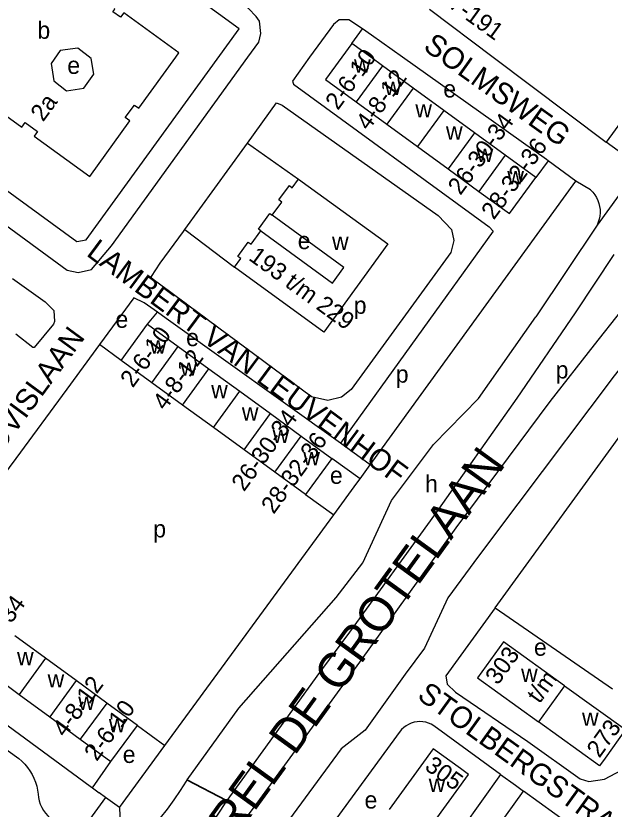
# Model space of a CAD drawing. Extents: x 159700 to 161346, y 381730 to 382922.
# Drawn here: x 160111.3 to 160249.2, y 382258.8 to 382442.9 of the extents above; entities that cross this region are included whole.
import ezdxf

# ---------------------------------------------------------------- set-up
doc = ezdxf.new("R2010")
doc.units = 0
for name, color, linetype in [('BLT_Basislijn', 7, 'Continuous'), ('BLT_Bebouwing', 7, 'Continuous'), ('BLT_Centroide', 7, 'Continuous'), ('BLT_Huisnummer', 7, 'Continuous'), ('BLT_Huisnummer_reeks', 7, 'Continuous'), ('BLT_Onderverdeling_panden', 7, 'Continuous'), ('BLT_Straatnaam', 7, 'Continuous'), ('BLT_Straatnaam_hoofdweg', 7, 'Continuous'), ('BLT_Vlakafsluiter', 7, 'Continuous')]:
    doc.layers.add(name, color=color, linetype=linetype)

msp = doc.modelspace()

# ---------------------------------------------------------------- linework, layer by layer
at = {"layer": 'BLT_Basislijn'}
for p, q in [((160189.26, 382436.52), (160191.7, 382439.88)), ((160165.04, 382413.38), (160176.87, 382405.03)), ((160252.43, 382410.59), (160248.24, 382413.61)), ((160234.75, 382409.29), (160231.92, 382405.42)), ((160241.19, 382404.58), (160234.75, 382409.29)), ((160193.53, 382338.74), (160241.19, 382404.58)), ((160244.62, 382402.5), (160241.19, 382404.58)), ((160150.52, 382393.35), (160162.02, 382384.61)), ((160246.12, 382394.33), (160231.92, 382373.05)), ((160250.04, 382387.54), (160241.05, 382374.01)), ((160141.86, 382371.33), (160144.19, 382374.14)), ((160241.05, 382374.01), (160227.5, 382354.17)), ((160130.73, 382366.61), (160123.15, 382356.29)), ((160135.76, 382362.95), (160130.73, 382366.61)), ((160222.52, 382305.55), (160263.56, 382362.17)), ((160123.15, 382356.29), (160111.33, 382340.21)), ((160227.5, 382354.17), (160208.45, 382327.12)), ((160235.17, 382353.39), (160213.4, 382324.1)), ((160193.53, 382338.74), (160186.59, 382343.72)), ((160111.33, 382340.21), (160108.18, 382335.98)), ((160191.15, 382335.45), (160184.59, 382340.23)), ((160191.15, 382335.45), (160193.53, 382338.74)), ((160178.49, 382331.85), (160185.05, 382327.12)), ((160145.86, 382273.59), (160185.05, 382327.12)), ((160213.4, 382324.1), (160191.02, 382292.94)), ((160222.52, 382305.55), (160249.67, 382286.74)), ((160191.02, 382292.94), (160167.79, 382261.09)), ((160089.95, 382286.38), (160111.96, 382270.56)), ((160139.51, 382278.26), (160145.86, 382273.59)), ((160223.73, 382266.87), (160208.27, 382278.18)), ((160200.46, 382276.89), (160179.29, 382248.03)), ((160135.33, 382259.22), (160145.86, 382273.59)), ((160129.06, 382263.8), (160133.36, 382269.85)), ((160223.73, 382266.87), (160191.03, 382221.18)), ((160129.06, 382263.8), (160130.61, 382262.6)), ((160132.12, 382261.51), (160130.61, 382262.6)), ((160221.28, 382252.22), (160229.09, 382263)), ((160135.33, 382259.22), (160132.12, 382261.51)), ((160167.79, 382261.09), (160160.39, 382250.98))]:
    msp.add_line(p, q, dxfattribs=at)
for points in [[(160055.58, 382436.89), (160053.86, 382434.1), (160054.93, 382433.33), (160088.85, 382409.04), (160123.19, 382383.92), (160125.73, 382383.39), (160128.86, 382384.06), (160133.46, 382389.51), (160165.14, 382433.33), (160167.65, 382436.8), (160168.16, 382438.78), (160167.81, 382441.67), (160167.07, 382442.79), (160165.27, 382444.61), (160155.77, 382451.87), (160099.41, 382492.45), (160096.79, 382493.83), (160095.82, 382492.52)], [(160059.6, 382438.55), (160125.46, 382390.57), (160127.6, 382390.97), (160163.12, 382439.91), (160095.62, 382488.95)], [(160293.83, 382476.2), (160293.16, 382475.27), (160262.61, 382433.33), (160248.24, 382413.61)], [(160207.26, 382444.45), (160222.03, 382433.33), (160248.24, 382413.61)], [(160191.7, 382439.88), (160188.55, 382441.99), (160186.32, 382442.02), (160184.96, 382440.88), (160179.42, 382433.33), (160175.49, 382427.79), (160175.68, 382427.09), (160221.08, 382393.97), (160222.03, 382392.92), (160186.59, 382343.72)], [(160234.75, 382409.29), (160234.37, 382409.56), (160201.02, 382433.33), (160193.84, 382438.46), (160191.7, 382439.88)], [(160165.04, 382413.38), (160171.79, 382422.72), (160173.06, 382422.18), (160209.25, 382396.61), (160212.35, 382393.33), (160212.92, 382390.79), (160212.18, 382387.99), (160189.12, 382356.18), (160186.83, 382354.42), (160183.65, 382353.66), (160179.9, 382354.53), (160142.84, 382381.98), (160142.79, 382382.45), (160144.82, 382385.53), (160150.16, 382392.86), (160150.52, 382393.35)], [(160150.52, 382393.35), (160164.45, 382412.55), (160165.04, 382413.38)], [(160244.62, 382402.5), (160245.13, 382401.97), (160245.59, 382401.39), (160245.98, 382400.76), (160246.3, 382400.09), (160246.55, 382399.39), (160246.72, 382398.67), (160246.81, 382397.94), (160246.82, 382397.2), (160246.75, 382396.46), (160246.61, 382395.74), (160246.38, 382395.03), (160246.12, 382394.33)], [(160168.14, 382393.01), (160167.62, 382393.43), (160170.23, 382397.02), (160170.77, 382396.63)], [(160110.52, 382381.97), (160118.13, 382376.57), (160120.11, 382374.57), (160120.26, 382372.01), (160120.01, 382371.39), (160115.53, 382365.97), (160115.28, 382365.97), (160111.29, 382369.02)], [(160268.06, 382382.16), (160250.09, 382359.39), (160227.78, 382329.64), (160218.64, 382317.56)], [(160257.68, 382382.01), (160245.47, 382366.57), (160235.17, 382353.39)], [(160144.19, 382374.14), (160141.08, 382376.34), (160138.71, 382377.48), (160130.73, 382366.61)], [(160186.59, 382343.72), (160146.21, 382372.71), (160144.19, 382374.14)], [(160198.47, 382330.41), (160208.22, 382343.46), (160218.6, 382354.15), (160231.92, 382373.05)], [(160185.05, 382327.12), (160190.44, 382334.48), (160191.15, 382335.45)], [(160151.03, 382265.6), (160163, 382282.24), (160185.61, 382307.95), (160191.81, 382316), (160198.47, 382330.41)], [(160208.45, 382327.12), (160188.7, 382299.92), (160181.73, 382290.54)], [(160218.64, 382317.56), (160211.51, 382307.82), (160206.09, 382296.19), (160201.61, 382290.12)], [(160222.52, 382305.55), (160211.06, 382289.75), (160211.38, 382287.84), (160213.29, 382285.99), (160230.06, 382274.53), (160242.18, 382265.83), (160244.2, 382265.24), (160247.86, 382265.74), (160264.1, 382274.33), (160265.12, 382275.17), (160265.4, 382275.55)], [(160087.42, 382292.85), (160091.58, 382291.34), (160128.55, 382264.19), (160129.06, 382263.8)], [(160181.73, 382290.54), (160165.93, 382268.68), (160160.23, 382260.82)], [(160201.61, 382290.12), (160192.3, 382277.12), (160186.73, 382272.79), (160170.03, 382250.04)], [(160208.27, 382278.18), (160207.67, 382278.53), (160207.05, 382278.79), (160206.39, 382278.99), (160205.72, 382279.11), (160205.04, 382279.14), (160204.36, 382279.1), (160203.68, 382278.98), (160203.03, 382278.78), (160202.41, 382278.5), (160201.82, 382278.16), (160201.27, 382277.74), (160200.78, 382277.27), (160200.46, 382276.89)], [(160111.96, 382270.56), (160112.7, 382269.93), (160113.39, 382269.24), (160114.02, 382268.5), (160114.58, 382267.71), (160115.08, 382266.87), (160115.51, 382266), (160115.87, 382265.09), (160116.15, 382264.16), (160116.35, 382263.2), (160116.47, 382262.31)], [(160223.73, 382266.87), (160227.21, 382264.37), (160229.09, 382263)], [(160114.46, 382232.74), (160116.8, 382233.88), (160119.11, 382235.1), (160121.38, 382236.38), (160123.61, 382237.74), (160125.79, 382239.16), (160127.93, 382240.65), (160130.03, 382242.2), (160132.07, 382243.82), (160134.07, 382245.5), (160136.01, 382247.24), (160137.9, 382249.04), (160139.73, 382250.9), (160141.51, 382252.81), (160143.23, 382254.77), (160144.88, 382256.79), (160146.47, 382258.85), (160148, 382260.97), (160149.46, 382263.13), (160150.86, 382265.33), (160151, 382265.56)], [(160151, 382265.56), (160151.03, 382265.6)], [(160116.47, 382262.31), (160116.56, 382261.52), (160116.74, 382260.73), (160116.98, 382259.97), (160117.31, 382259.24), (160117.7, 382258.54), (160118.16, 382257.89), (160118.69, 382257.29), (160119.27, 382256.74), (160119.88, 382256.27)], [(160267.47, 382258.69), (160243.6, 382252.44), (160229.09, 382263)], [(160132.12, 382261.51), (160125.53, 382252.48), (160119.88, 382256.27)], [(160160.2, 382260.78), (160158.66, 382258.38), (160157.05, 382256.02), (160155.37, 382253.71), (160153.64, 382251.44), (160151.83, 382249.23), (160149.97, 382247.07), (160148.05, 382244.96), (160146.07, 382242.9), (160144.03, 382240.9), (160141.94, 382238.96), (160139.79, 382237.08), (160137.59, 382235.26), (160135.35, 382233.5), (160133.05, 382231.81), (160130.71, 382230.18), (160129.76, 382229.55)], [(160160.23, 382260.82), (160160.2, 382260.78)], [(160135.33, 382259.22), (160135.59, 382253.44), (160131.88, 382249.87)]]:
    msp.add_lwpolyline(points, dxfattribs=at)
at = {"layer": 'BLT_Bebouwing'}
for p, q in [((160203.48, 382426.15), (160196.37, 382431.33)), ((160210.59, 382420.97), (160203.48, 382426.15)), ((160190.24, 382422.93), (160197.35, 382417.74)), ((160217.7, 382415.78), (160210.59, 382420.97)), ((160197.35, 382417.74), (160204.46, 382412.56)), ((160224.81, 382410.6), (160217.7, 382415.78)), ((160204.46, 382412.56), (160211.57, 382407.38)), ((160231.92, 382405.42), (160224.81, 382410.6)), ((160211.57, 382407.38), (160218.68, 382402.19)), ((160135.76, 382362.95), (160141.86, 382371.33)), ((160141.86, 382371.33), (160148.98, 382366.15)), ((160148.98, 382366.15), (160156.1, 382360.97)), ((160142.88, 382357.77), (160135.76, 382362.95)), ((160156.1, 382360.97), (160163.23, 382355.78)), ((160150, 382352.58), (160142.88, 382357.77)), ((160163.23, 382355.78), (160170.35, 382350.6)), ((160157.12, 382347.4), (160150, 382352.58)), ((160170.35, 382350.6), (160177.47, 382345.41)), ((160164.25, 382342.21), (160157.12, 382347.4)), ((160177.47, 382345.41), (160184.59, 382340.23)), ((160171.37, 382337.03), (160164.25, 382342.21)), ((160184.59, 382340.23), (160178.49, 382331.85)), ((160178.49, 382331.85), (160171.37, 382337.03)), ((160118.2, 382293.84), (160111.1, 382299.03)), ((160125.3, 382288.65), (160118.2, 382293.84)), ((160104.95, 382290.62), (160112.05, 382285.43)), ((160132.41, 382283.45), (160125.3, 382288.65)), ((160112.05, 382285.43), (160119.15, 382280.23)), ((160139.51, 382278.26), (160132.41, 382283.45)), ((160119.15, 382280.23), (160126.26, 382275.04)), ((160133.36, 382269.85), (160139.51, 382278.26)), ((160126.26, 382275.04), (160133.36, 382269.85))]:
    msp.add_line(p, q, dxfattribs=at)
for points in [[(160099.75, 382426.44), (160112.67, 382417.06), (160113.45, 382418.13), (160116.31, 382416.06), (160115.54, 382415), (160128.43, 382405.64), (160137.78, 382418.52), (160136.7, 382419.3), (160138.81, 382422.22), (160139.83, 382421.48), (160148.43, 382433.33), (160149.15, 382434.32), (160136.32, 382443.63), (160135.58, 382442.61), (160133.84, 382443.87), (160134.28, 382444.49), (160134.12, 382444.61)], [(160189.26, 382436.52), (160186.93, 382433.33), (160183.13, 382428.11), (160190.24, 382422.93)], [(160196.37, 382431.33), (160193.62, 382433.33), (160189.26, 382436.52)], [(160176.87, 382405.03), (160197.61, 382389.99), (160182.78, 382369.54), (160162.02, 382384.61)], [(160170.77, 382396.63), (160173.01, 382399.71), (160172.34, 382400.19), (160174.76, 382403.53), (160175.43, 382403.04), (160176.87, 382405.03)], [(160218.68, 382402.19), (160225.8, 382397.01), (160231.92, 382405.42)], [(160168.14, 382393.01), (160184.78, 382380.91), (160187.42, 382384.53), (160170.77, 382396.63)], [(160162.02, 382384.61), (160163.47, 382386.6), (160162.8, 382387.08), (160165.23, 382390.42), (160165.9, 382389.93), (160168.14, 382393.01)], [(160238.59, 382287.46), (160224.46, 382297.64), (160219.42, 382290.68), (160218.4, 382289.26), (160232.54, 382279.07)], [(160238.59, 382287.46), (160252.72, 382277.28), (160247.97, 382270.68), (160246.68, 382268.88), (160232.54, 382279.07)], [(160206.07, 382252.8), (160216.28, 382266.89), (160214.44, 382268.23), (160208.07, 382272.81), (160197.87, 382258.75)]]:
    msp.add_lwpolyline(points, dxfattribs=at)
msp.add_lwpolyline([(160125.65, 382435.43), (160121.62, 382434.84), (160119.49, 382431.82), (160120.15, 382427.8), (160123.09, 382425.53), (160127.09, 382426.11), (160129.39, 382429.4), (160128.79, 382433.01)], close=True, dxfattribs=at)
at = {"layer": 'BLT_Onderverdeling_panden'}
for p, q in [((160196.37, 382431.33), (160190.24, 382422.93)), ((160203.48, 382426.15), (160197.35, 382417.74)), ((160210.59, 382420.97), (160204.46, 382412.56)), ((160217.7, 382415.78), (160211.57, 382407.38)), ((160224.81, 382410.6), (160218.68, 382402.19)), ((160142.88, 382357.77), (160148.98, 382366.15)), ((160150, 382352.58), (160156.1, 382360.97)), ((160157.12, 382347.4), (160163.23, 382355.78)), ((160164.25, 382342.21), (160170.35, 382350.6)), ((160171.37, 382337.03), (160177.47, 382345.41)), ((160118.2, 382293.84), (160112.05, 382285.43)), ((160125.3, 382288.65), (160119.15, 382280.23)), ((160238.59, 382287.46), (160232.54, 382279.07)), ((160132.41, 382283.45), (160126.26, 382275.04))]:
    msp.add_line(p, q, dxfattribs=at)
at = {"layer": 'BLT_Vlakafsluiter'}
for p, q in [((160258.48, 382411.43), (160246.12, 382394.33)), ((160160.2, 382260.78), (160151, 382265.56)), ((160160.23, 382260.82), (160151.03, 382265.6))]:
    msp.add_line(p, q, dxfattribs=at)

# ---------------------------------------------------------------- texts
at = {"layer": 'BLT_Centroide'}
for s, p in [('b', (160116.31, 382437.59)), ('e', (160123.24, 382429.44)), ('w', (160189.75, 382429.72)), ('w', (160196.86, 382424.53)), ('e', (160210.46, 382423.97)), ('w', (160203.97, 382419.34)), ('w', (160211.08, 382414.17)), ('w', (160218.19, 382409)), ('w', (160225.3, 382403.81)), ('e', (160176.69, 382388.78)), ('w', (160184.64, 382388.59)), ('p', (160189.68, 382373.76)), ('e', (160134.41, 382370.52)), ('e', (160150.8, 382366.27)), ('w', (160142.38, 382364.55)), ('w', (160149.48, 382359.38)), ('p', (160236.52, 382358.76)), ('p', (160199.43, 382357.79)), ('w', (160156.61, 382354.19)), ('w', (160163.73, 382349)), ('w', (160170.86, 382343.81)), ('w', (160177.98, 382338.62)), ('e', (160184.16, 382334.31)), ('h', (160206.22, 382332.33)), ('p', (160143.17, 382321.87)), ('e', (160231.49, 382294.42)), ('w', (160111.58, 382292.23)), ('w', (160118.67, 382287.05)), ('w', (160228.5, 382288.34)), ('w', (160125.78, 382281.84)), ('w', (160242.63, 382278.16)), ('w', (160132.88, 382276.64)), ('e', (160136.1, 382269.54)), ('w', (160207.08, 382262.81)), ('e', (160192.19, 382258.96))]:
    msp.add_text(s, height=4, dxfattribs=at).set_placement(p)
at = {"layer": 'BLT_Huisnummer'}
msp.add_text('2a', height=4, rotation=54.0335, dxfattribs=at).set_placement((160117.63, 382418.16))
at = {"layer": 'BLT_Huisnummer_reeks'}
for s, rotation, p in [('183-187-191', 324.0736, (160197.94, 382454.85)), ('2-6-10', 53.9535, (160186.01, 382420.84)), ('4-8-12', 53.9111, (160193.09, 382416.09)), ('26-30-34', 53.9155, (160214.43, 382401.11)), ('28-32-36', 53.9155, (160222.18, 382395.4)), ('193 t/m 229', 324.0125, (160165.08, 382386.42)), ('2-6-10', 53.9535, (160138.43, 382356.43)), ('4-8-12', 53.9503, (160145.94, 382351.13)), ('26-30-34', 53.9515, (160164.23, 382332.33)), ('28-32-36', 53.9458, (160171.11, 382327.1)), ('26-30-34', 53.8307, (160101.09, 382289.26)), ('303', 54.129, (160223.11, 382287.43)), ('t/m', 54.2722, (160232.76, 382283.13)), ('4-8-12', 53.8307, (160122.7, 382275.31)), ('2-6-10', 53.8307, (160130.07, 382269.75)), ('273', 54.2722, (160246.66, 382270.51)), ('305', 324.0649, (160205.91, 382268.2))]:
    msp.add_text(s, height=4, rotation=rotation, dxfattribs=at).set_placement(p)
at = {"layer": 'BLT_Straatnaam'}
for s, height, rotation, p in [('SOLMSWEG', 5, 324.5166, (160205.57, 382435.2)), ('LAMBERT VAN LEUVENHOF', 4.9999, 323.4703, (160127.44, 382387.41)), ('CLOVISLAAN', 5, 53.6983, (160102.69, 382334.49)), ('STOLBERGSTRAAT', 4.9999, 324.2351, (160204.15, 382284.63))]:
    msp.add_text(s, height=height, rotation=rotation, dxfattribs=at).set_placement(p)
at = {"layer": 'BLT_Straatnaam_hoofdweg'}
msp.add_text('KAREL DE GROTELAAN', height=7.9999, rotation=54.0827, dxfattribs=at).set_placement((160153.64, 382240.2))

doc.saveas('drawing.dxf')
